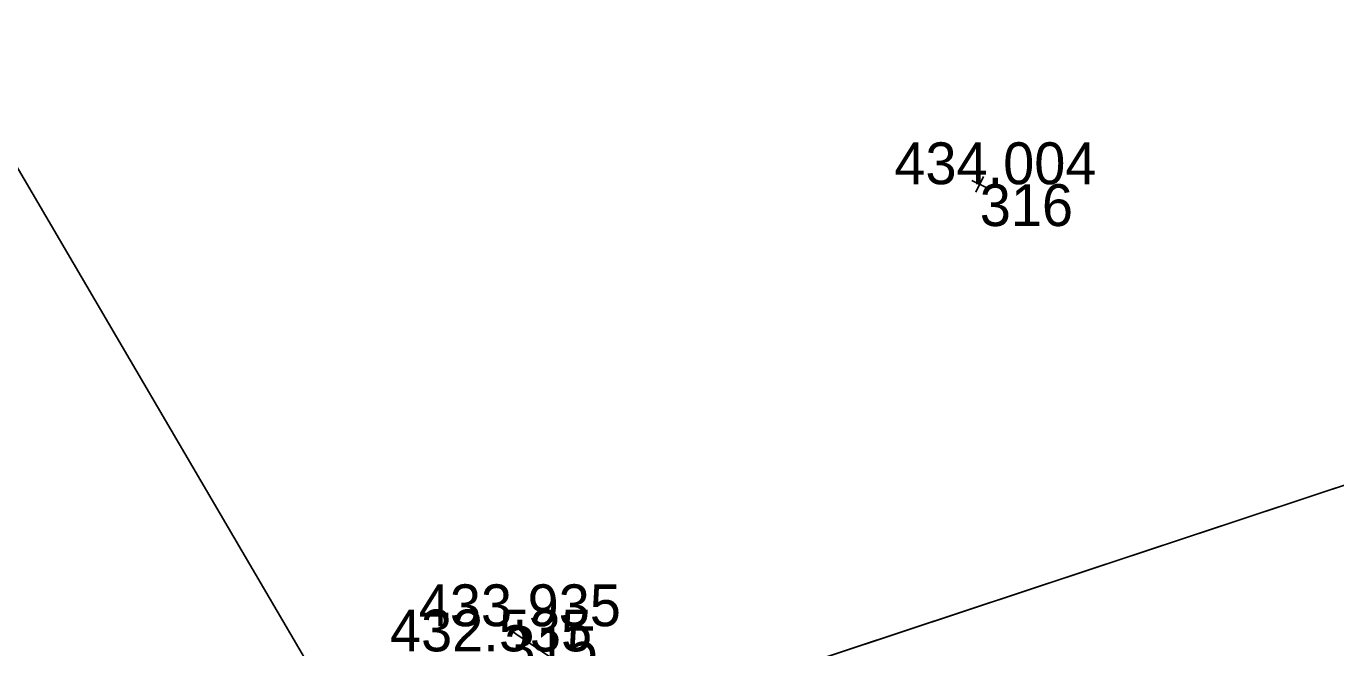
# Model space of a CAD drawing. Extents: x -776734 to -748832, y -1118122 to -976986.
# Drawn here: x -751173.31 to -751135.72, y -1114669.8 to -1114651.97 of the extents above; entities that cross this region are included whole.
import ezdxf

# ---------------------------------------------------------------- set-up
doc = ezdxf.new("R2010")
doc.units = 0
for name, color, linetype in [('KM_Hranice parcel', 7, 'Continuous'), ('Obvod stavby - SŽ+ČD', 7, 'Continuous'), ('SŽG Vrstva 49', 7, 'Continuous'), ('SŽG Vrstva 53', 7, 'Continuous'), ('SŽG Vrstva 60', 7, 'Continuous'), ('SŽG Vrstva 61', 7, 'Continuous')]:
    doc.layers.add(name, color=color, linetype=linetype)

msp = doc.modelspace()

# ---------------------------------------------------------------- linework, layer by layer
at = {"layer": 'KM_Hranice parcel'}
msp.add_line((-751162.9, -1114674.22), (-751118.39, -1114659.47), dxfattribs=at)
msp.add_lwpolyline([(-751248.93, -1114484.17), (-751256.66, -1114493), (-751183.62, -1114634.05), (-751176.58, -1114650.88), (-751162.9, -1114674.22)], dxfattribs=at)
at = {"layer": 'Obvod stavby - SŽ+ČD'}
msp.add_lwpolyline([(-751236.9, -1114707.02), (-751193.03, -1114664.28), (-751178.42, -1114675.26), (-751174.34, -1114678.03), (-751170.9473, -1114676.9001), (-751168.1235, -1114675.9597), (-751162.9, -1114674.22), (-751118.39, -1114659.47), (-751098.21, -1114652.66), (-751091.59, -1114651.24), (-751052.09, -1114634.98), (-751042.9845, -1114631.6438), (-751001.9301, -1114630.5149), (-750919.7259, -1114602.1536)], dxfattribs=at)
at = {"layer": 'SŽG Vrstva 49'}
for p, q in [((-751145.7153, -1114656.6105), (-751146.1647, -1114656.3915)), ((-751145.8305, -1114656.2763), (-751146.0495, -1114656.7257))]:
    msp.add_line(p, q, dxfattribs=at)
msp.add_lwpolyline([(-751159.583, -1114669.179), (-751152.304, -1114674.09), (-751146.04, -1114682.559), (-751140.899, -1114695.046), (-751135.289, -1114707.45), (-751130.657, -1114726.726)], dxfattribs=at)
at = {"layer": 'SŽG Vrstva 53'}
msp.add_lwpolyline([(-751615.07, -1114840.52), (-751596.62, -1114835), (-751572.02, -1114827.5), (-751551.31, -1114808.23), (-751526.51, -1114811.39), (-751501.68, -1114801.88), (-751460.63, -1114785.23), (-751418.82, -1114768.72), (-751390.21, -1114757.9), (-751377.2, -1114753.63), (-751337.18, -1114740.99), (-751293.44, -1114727.24), (-751276.39, -1114722.19), (-751236.9, -1114707.02), (-751193.03, -1114664.28), (-751178.42, -1114675.26), (-751174.34, -1114678.03), (-751162.9, -1114674.22), (-751118.39, -1114659.47), (-751098.21, -1114652.66), (-751091.59, -1114651.24)], dxfattribs=at)
at = {"layer": 'SŽG Vrstva 60'}
for p, q in [((-751145.94, -1114656.501), (-751145.94, -1114656.501)), ((-751159.583, -1114669.179), (-751159.583, -1114669.179))]:
    msp.add_line(p, q, dxfattribs=at)

# ---------------------------------------------------------------- texts
for s, p in [('316', (-751145.94, -1114657.701)), ('315', (-751159.583, -1114670.379))]:
    msp.add_text(s, height=1.2, dxfattribs=at).set_placement(p)
at = {"layer": 'SŽG Vrstva 61'}
for s, p in [('434.004', (-751148.391, -1114656.501)), ('433.935', (-751162.0391, -1114669.179)), ('432.535', (-751162.8651, -1114669.901))]:
    msp.add_text(s, height=1.2, dxfattribs=at).set_placement(p)

doc.saveas('drawing.dxf')
